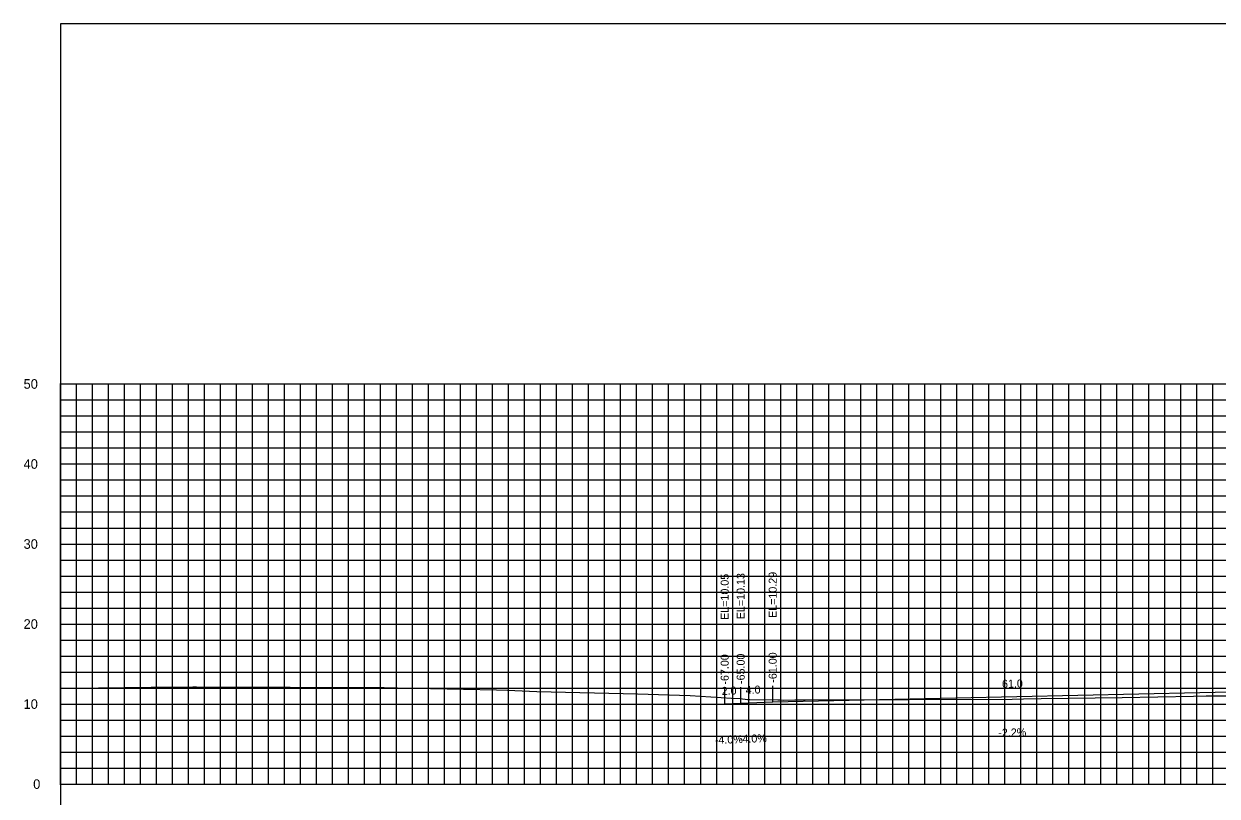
# Model space of a CAD drawing. Extents: x 1797419 to 1809236, y 248759 to 251512.
# Drawn here: x 1803156.4 to 1803305.5, y 250510.8 to 250607.3 of the extents above; entities that cross this region are included whole.
import ezdxf

# ---------------------------------------------------------------- set-up
doc = ezdxf.new("R2010")
doc.units = 0
for name, color, linetype in [('3', 7, 'Continuous'), ('31', 7, 'Continuous'), ('4', 7, 'Continuous'), ('60', 7, 'Continuous'), ('CL-CNST', 7, 'Continuous'), ('Level 62', 7, 'Continuous'), ('M-ROADS', 7, 'Continuous')]:
    doc.layers.add(name, color=color, linetype=linetype)

msp = doc.modelspace()

# ---------------------------------------------------------------- linework, layer by layer
for p, q in [((1803244, 250522.31), (1803244, 250524.31)), ((1803246, 250522.39), (1803246, 250524.39)), ((1803250, 250522.55), (1803250, 250524.55))]:
    msp.add_line(p, q)
msp.add_lwpolyline([(1803161, 250417.26), (1803461, 250417.26), (1803461, 250607.26), (1803161, 250607.26)], close=True)
at = {"layer": '60'}
for p, q in [((1803160.94, 250562.26), (1803161, 250562.26)), ((1803161, 250512.26), (1803161, 250562.26)), ((1803160.94, 250552.26), (1803161, 250552.26)), ((1803160.94, 250542.26), (1803161, 250542.26)), ((1803160.94, 250532.26), (1803161, 250532.26)), ((1803160.94, 250522.26), (1803161, 250522.26)), ((1803160.94, 250512.26), (1803161, 250512.26)), ((1803161, 250512.26), (1803461, 250512.26)), ((1803161, 250512.2), (1803161, 250512.26)), ((1803171, 250512.2), (1803171, 250512.26)), ((1803181, 250512.2), (1803181, 250512.26)), ((1803191, 250512.2), (1803191, 250512.26)), ((1803201, 250512.2), (1803201, 250512.26)), ((1803211, 250512.2), (1803211, 250512.26)), ((1803221, 250512.2), (1803221, 250512.26)), ((1803231, 250512.2), (1803231, 250512.26)), ((1803241, 250512.2), (1803241, 250512.26)), ((1803251, 250512.2), (1803251, 250512.26)), ((1803261, 250512.2), (1803261, 250512.26)), ((1803271, 250512.2), (1803271, 250512.26)), ((1803281, 250512.2), (1803281, 250512.26)), ((1803291, 250512.2), (1803291, 250512.26)), ((1803301, 250512.2), (1803301, 250512.26))]:
    msp.add_line(p, q, dxfattribs=at)
at = {"layer": 'CL-CNST'}
msp.add_lwpolyline([(1803244, 250522.31), (1803246, 250522.39), (1803250, 250522.55), (1803311, 250523.89), (1803361.63, 250525), (1803365.63, 250524.84), (1803367.63, 250524.76)], dxfattribs=at)
at = {"layer": 'Level 62'}
for p, q in [((1803161, 250562.26), (1803461, 250562.26)), ((1803161, 250512.26), (1803161, 250562.26)), ((1803161, 250562.26), (1803461, 250562.26)), ((1803161, 250512.26), (1803161, 250562.26)), ((1803163, 250512.26), (1803163, 250562.26)), ((1803163, 250512.26), (1803163, 250562.26)), ((1803165, 250512.26), (1803165, 250562.26)), ((1803165, 250512.26), (1803165, 250562.26)), ((1803167, 250512.26), (1803167, 250562.26)), ((1803167, 250512.26), (1803167, 250562.26)), ((1803169, 250512.26), (1803169, 250562.26)), ((1803169, 250512.26), (1803169, 250562.26)), ((1803171, 250512.26), (1803171, 250562.26)), ((1803171, 250512.26), (1803171, 250562.26)), ((1803173, 250512.26), (1803173, 250562.26)), ((1803173, 250512.26), (1803173, 250562.26)), ((1803175, 250512.26), (1803175, 250562.26)), ((1803175, 250512.26), (1803175, 250562.26)), ((1803177, 250512.26), (1803177, 250562.26)), ((1803177, 250512.26), (1803177, 250562.26)), ((1803179, 250512.26), (1803179, 250562.26)), ((1803179, 250512.26), (1803179, 250562.26)), ((1803181, 250512.26), (1803181, 250562.26)), ((1803181, 250512.26), (1803181, 250562.26)), ((1803183, 250512.26), (1803183, 250562.26)), ((1803183, 250512.26), (1803183, 250562.26)), ((1803185, 250512.26), (1803185, 250562.26)), ((1803185, 250512.26), (1803185, 250562.26)), ((1803187, 250512.26), (1803187, 250562.26)), ((1803187, 250512.26), (1803187, 250562.26)), ((1803189, 250512.26), (1803189, 250562.26)), ((1803189, 250512.26), (1803189, 250562.26)), ((1803191, 250512.26), (1803191, 250562.26)), ((1803191, 250512.26), (1803191, 250562.26)), ((1803193, 250512.26), (1803193, 250562.26)), ((1803193, 250512.26), (1803193, 250562.26)), ((1803195, 250512.26), (1803195, 250562.26)), ((1803195, 250512.26), (1803195, 250562.26)), ((1803197, 250512.26), (1803197, 250562.26)), ((1803197, 250512.26), (1803197, 250562.26)), ((1803199, 250512.26), (1803199, 250562.26)), ((1803199, 250512.26), (1803199, 250562.26)), ((1803201, 250512.26), (1803201, 250562.26)), ((1803201, 250512.26), (1803201, 250562.26)), ((1803203, 250512.26), (1803203, 250562.26)), ((1803203, 250512.26), (1803203, 250562.26)), ((1803205, 250512.26), (1803205, 250562.26)), ((1803205, 250512.26), (1803205, 250562.26)), ((1803207, 250512.26), (1803207, 250562.26)), ((1803207, 250512.26), (1803207, 250562.26)), ((1803209, 250512.26), (1803209, 250562.26)), ((1803209, 250512.26), (1803209, 250562.26)), ((1803211, 250512.26), (1803211, 250562.26)), ((1803211, 250512.26), (1803211, 250562.26)), ((1803213, 250512.26), (1803213, 250562.26)), ((1803213, 250512.26), (1803213, 250562.26)), ((1803215, 250512.26), (1803215, 250562.26)), ((1803215, 250512.26), (1803215, 250562.26)), ((1803217, 250512.26), (1803217, 250562.26)), ((1803217, 250512.26), (1803217, 250562.26)), ((1803219, 250512.26), (1803219, 250562.26)), ((1803219, 250512.26), (1803219, 250562.26)), ((1803221, 250512.26), (1803221, 250562.26)), ((1803221, 250512.26), (1803221, 250562.26)), ((1803223, 250512.26), (1803223, 250562.26)), ((1803223, 250512.26), (1803223, 250562.26)), ((1803225, 250512.26), (1803225, 250562.26)), ((1803225, 250512.26), (1803225, 250562.26)), ((1803227, 250512.26), (1803227, 250562.26)), ((1803227, 250512.26), (1803227, 250562.26)), ((1803229, 250512.26), (1803229, 250562.26)), ((1803229, 250512.26), (1803229, 250562.26)), ((1803231, 250512.26), (1803231, 250562.26)), ((1803231, 250512.26), (1803231, 250562.26)), ((1803233, 250512.26), (1803233, 250562.26)), ((1803233, 250512.26), (1803233, 250562.26)), ((1803235, 250512.26), (1803235, 250562.26)), ((1803235, 250512.26), (1803235, 250562.26)), ((1803237, 250512.26), (1803237, 250562.26)), ((1803237, 250512.26), (1803237, 250562.26)), ((1803239, 250512.26), (1803239, 250562.26)), ((1803239, 250512.26), (1803239, 250562.26)), ((1803241, 250512.26), (1803241, 250562.26)), ((1803241, 250512.26), (1803241, 250562.26)), ((1803243, 250512.26), (1803243, 250562.26)), ((1803243, 250512.26), (1803243, 250562.26)), ((1803245, 250512.26), (1803245, 250562.26)), ((1803245, 250512.26), (1803245, 250562.26)), ((1803247, 250512.26), (1803247, 250562.26)), ((1803247, 250512.26), (1803247, 250562.26)), ((1803249, 250512.26), (1803249, 250562.26)), ((1803249, 250512.26), (1803249, 250562.26)), ((1803251, 250512.26), (1803251, 250562.26)), ((1803251, 250512.26), (1803251, 250562.26)), ((1803253, 250512.26), (1803253, 250562.26)), ((1803253, 250512.26), (1803253, 250562.26)), ((1803255, 250512.26), (1803255, 250562.26)), ((1803255, 250512.26), (1803255, 250562.26)), ((1803257, 250512.26), (1803257, 250562.26)), ((1803257, 250512.26), (1803257, 250562.26)), ((1803259, 250512.26), (1803259, 250562.26)), ((1803259, 250512.26), (1803259, 250562.26)), ((1803261, 250512.26), (1803261, 250562.26)), ((1803261, 250512.26), (1803261, 250562.26)), ((1803263, 250512.26), (1803263, 250562.26)), ((1803263, 250512.26), (1803263, 250562.26)), ((1803265, 250512.26), (1803265, 250562.26)), ((1803265, 250512.26), (1803265, 250562.26)), ((1803267, 250512.26), (1803267, 250562.26)), ((1803267, 250512.26), (1803267, 250562.26)), ((1803269, 250512.26), (1803269, 250562.26)), ((1803269, 250512.26), (1803269, 250562.26)), ((1803271, 250512.26), (1803271, 250562.26)), ((1803271, 250512.26), (1803271, 250562.26)), ((1803273, 250512.26), (1803273, 250562.26)), ((1803273, 250512.26), (1803273, 250562.26)), ((1803275, 250512.26), (1803275, 250562.26)), ((1803275, 250512.26), (1803275, 250562.26)), ((1803277, 250512.26), (1803277, 250562.26)), ((1803277, 250512.26), (1803277, 250562.26)), ((1803279, 250512.26), (1803279, 250562.26)), ((1803279, 250512.26), (1803279, 250562.26)), ((1803281, 250512.26), (1803281, 250562.26)), ((1803281, 250512.26), (1803281, 250562.26)), ((1803283, 250512.26), (1803283, 250562.26)), ((1803283, 250512.26), (1803283, 250562.26)), ((1803285, 250512.26), (1803285, 250562.26)), ((1803285, 250512.26), (1803285, 250562.26)), ((1803287, 250512.26), (1803287, 250562.26)), ((1803287, 250512.26), (1803287, 250562.26)), ((1803289, 250512.26), (1803289, 250562.26)), ((1803289, 250512.26), (1803289, 250562.26)), ((1803291, 250512.26), (1803291, 250562.26)), ((1803291, 250512.26), (1803291, 250562.26)), ((1803293, 250512.26), (1803293, 250562.26)), ((1803293, 250512.26), (1803293, 250562.26)), ((1803295, 250512.26), (1803295, 250562.26)), ((1803295, 250512.26), (1803295, 250562.26)), ((1803297, 250512.26), (1803297, 250562.26)), ((1803297, 250512.26), (1803297, 250562.26)), ((1803299, 250512.26), (1803299, 250562.26)), ((1803299, 250512.26), (1803299, 250562.26)), ((1803301, 250512.26), (1803301, 250562.26)), ((1803301, 250512.26), (1803301, 250562.26)), ((1803303, 250512.26), (1803303, 250562.26)), ((1803303, 250512.26), (1803303, 250562.26)), ((1803305, 250512.26), (1803305, 250562.26)), ((1803305, 250512.26), (1803305, 250562.26)), ((1803161, 250560.26), (1803461, 250560.26)), ((1803161, 250560.26), (1803461, 250560.26)), ((1803161, 250558.26), (1803461, 250558.26)), ((1803161, 250558.26), (1803461, 250558.26)), ((1803161, 250556.26), (1803461, 250556.26)), ((1803161, 250556.26), (1803461, 250556.26)), ((1803161, 250554.26), (1803461, 250554.26)), ((1803161, 250554.26), (1803461, 250554.26)), ((1803161, 250552.26), (1803461, 250552.26)), ((1803161, 250552.26), (1803461, 250552.26)), ((1803161, 250550.26), (1803461, 250550.26)), ((1803161, 250550.26), (1803461, 250550.26)), ((1803161, 250548.26), (1803461, 250548.26)), ((1803161, 250548.26), (1803461, 250548.26)), ((1803161, 250546.26), (1803461, 250546.26)), ((1803161, 250546.26), (1803461, 250546.26)), ((1803161, 250544.26), (1803461, 250544.26)), ((1803161, 250544.26), (1803461, 250544.26)), ((1803161, 250542.26), (1803461, 250542.26)), ((1803161, 250542.26), (1803461, 250542.26)), ((1803161, 250540.26), (1803461, 250540.26)), ((1803161, 250540.26), (1803461, 250540.26)), ((1803161, 250538.26), (1803461, 250538.26)), ((1803161, 250538.26), (1803461, 250538.26)), ((1803161, 250536.26), (1803461, 250536.26)), ((1803161, 250536.26), (1803461, 250536.26)), ((1803161, 250534.26), (1803461, 250534.26)), ((1803161, 250534.26), (1803461, 250534.26)), ((1803161, 250532.26), (1803461, 250532.26)), ((1803161, 250532.26), (1803461, 250532.26)), ((1803161, 250530.26), (1803461, 250530.26)), ((1803161, 250530.26), (1803461, 250530.26)), ((1803161, 250528.26), (1803461, 250528.26)), ((1803161, 250528.26), (1803461, 250528.26)), ((1803161, 250526.26), (1803461, 250526.26)), ((1803161, 250526.26), (1803461, 250526.26)), ((1803161, 250524.26), (1803461, 250524.26)), ((1803161, 250524.26), (1803461, 250524.26)), ((1803161, 250522.26), (1803461, 250522.26)), ((1803161, 250522.26), (1803461, 250522.26)), ((1803161, 250520.26), (1803461, 250520.26)), ((1803161, 250520.26), (1803461, 250520.26)), ((1803161, 250518.26), (1803461, 250518.26)), ((1803161, 250518.26), (1803461, 250518.26)), ((1803161, 250516.26), (1803461, 250516.26)), ((1803161, 250516.26), (1803461, 250516.26)), ((1803161, 250514.26), (1803461, 250514.26)), ((1803161, 250514.26), (1803461, 250514.26)), ((1803161, 250512.26), (1803461, 250512.26)), ((1803161, 250512.26), (1803461, 250512.26))]:
    msp.add_line(p, q, dxfattribs=at)
at = {"layer": 'M-ROADS'}
msp.add_lwpolyline([(1803161, 250524.25), (1803165.78, 250524.29), (1803172.36, 250524.37), (1803177.56, 250524.4), (1803178.02, 250524.4), (1803201.47, 250524.31), (1803203.14, 250524.29), (1803215.51, 250524.04), (1803216.87, 250524), (1803220.52, 250523.83), (1803233.12, 250523.53), (1803239.7, 250523.32), (1803244.84, 250523.01), (1803245.94, 250522.94), (1803246.85, 250522.82), (1803247.01, 250522.82), (1803247.16, 250522.82), (1803250.63, 250522.8), (1803250.67, 250522.79), (1803250.74, 250522.79), (1803250.76, 250522.8), (1803250.92, 250522.8), (1803251.06, 250522.79), (1803251.4, 250522.73), (1803252.77, 250522.77), (1803254.07, 250522.8), (1803279.9, 250522.87), (1803281.34, 250522.91), (1803283.56, 250522.94), (1803293.66, 250523.09), (1803302.59, 250523.25), (1803304.15, 250523.27), (1803304.54, 250523.28), (1803307.01, 250523.27)], dxfattribs=at)

# ---------------------------------------------------------------- texts
at = {"layer": '3'}
for s, p in [('EL=10.29', (1803250.5, 250533.02)), ('EL=10.05', (1803244.5, 250532.78)), ('EL=10.13', (1803246.5, 250532.86)), ('-67.00', (1803244.5, 250524.69)), ('-65.00', (1803246.5, 250524.77)), ('-61.00', (1803250.5, 250524.93))]:
    msp.add_text(s, height=1, rotation=90, dxfattribs=at).set_placement(p)
at = {"layer": '31'}
for s, p in [('50', (1803156.4, 250561.66)), ('40', (1803156.4, 250551.66)), ('30', (1803156.4, 250541.66)), ('20', (1803156.4, 250531.66)), ('10', (1803156.4, 250521.66)), ('0', (1803157.6, 250511.66))]:
    msp.add_text(s, height=1.2, dxfattribs=at).set_placement(p)
at = {"layer": '4'}
for s, rotation, p in [('61.0', 1.2603, (1803278.66, 250524.28)), ('2.0', 2.2906, (1803243.64, 250523.39)), ('4.0', 2.2906, (1803246.64, 250523.51)), ('-4.0%', 2.2906, (1803242.79, 250517.26)), ('-4.0%', 2.2906, (1803245.79, 250517.38)), ('-2.2%', 1.2603, (1803278.2, 250518.17))]:
    msp.add_text(s, height=1, rotation=rotation, dxfattribs=at).set_placement(p)
at = {"layer": '60'}
msp.add_text('-', height=0.0001, dxfattribs=at).set_placement((1803161, 250512.26))

doc.saveas('drawing.dxf')
